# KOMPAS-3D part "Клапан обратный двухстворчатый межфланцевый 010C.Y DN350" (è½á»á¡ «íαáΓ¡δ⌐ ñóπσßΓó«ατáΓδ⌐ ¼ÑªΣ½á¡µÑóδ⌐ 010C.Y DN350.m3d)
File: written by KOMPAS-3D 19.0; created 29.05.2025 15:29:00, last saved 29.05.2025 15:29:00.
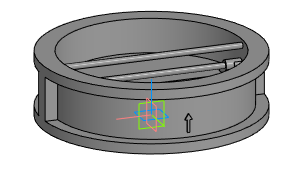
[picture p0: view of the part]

Document properties: Полное имя файла: E:\Dendor Работа Сачек\3D для проекитирвщиков\5.2 Тип 010C, 010C.Y Клапан обратный двухстворчатый межфланцевый\stp_Клапан обратный двухстворчатый межфланцевый 010C.Y\Клапан обратный двухстворчатый межфланцевый 010C.Y DN350.m3d

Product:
- Part/product: Клапан обратный двухстворчатый межфланцевый 010C.Y DN350

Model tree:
1. Операция без истории:1  (labels: Клапан обратный двухстворчатый межфланцевый 010C.Y DN350)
